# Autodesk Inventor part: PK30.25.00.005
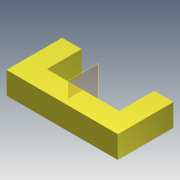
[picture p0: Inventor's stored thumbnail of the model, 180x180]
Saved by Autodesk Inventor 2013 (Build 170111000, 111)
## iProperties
Created: 2006-03
Part Number: PK30.25.00.005
Material: Steel, Mild
Document SubType Name: Modeling
Designer: SAlex
Manufacturer: Standard
Standards Organization: Custom
Density: 7.86 g/cm^3
Author: SAlex
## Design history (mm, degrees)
sketch "Эскиз1"
  geometry: L1 (0, 0)-(0, -40); L2 (0, -40)-(80, -40); L3 (80, -40)-(80, 0); L4 (80, 0)-(66, 0); L5 (66, 0)-(66, -25); L6 (66, -25)-(14, -25); L7 (14, -25)-(14, 0); L8 (14, 0)-(0, 0)
  constraints: 16 end point, 6 parallel, 2 collinear, 1 perpendicular, 1 vertical, 1 other
  dimensions: "d0" = 80 distance of L1.end L2.end; "d1" = 40 distance of L1.start L1.end; "d2" = 25 distance of L6.end L7.end; "d3" = 52 distance between parallel lines of L5 L7
extrude "Выдавливание1" new body sketch "Эскиз1" distance "d4" = 16; taper "d5" = 0 deg
workplane "Work Plane1"
body "Solid1"
